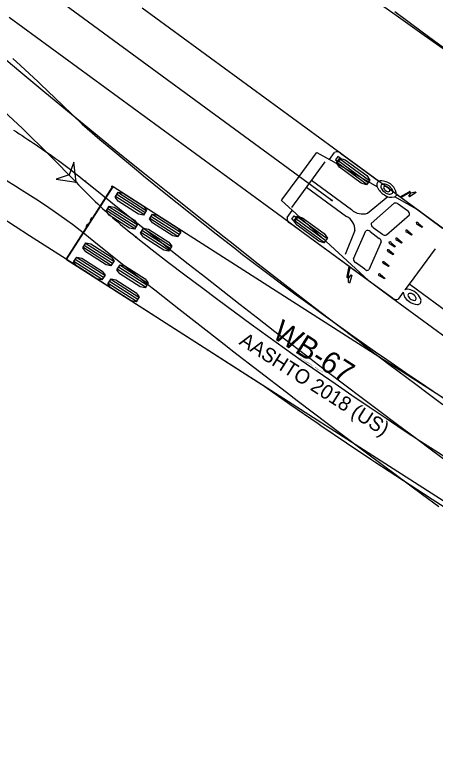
# Model space of a CAD drawing. Extents: x 973688 to 979179, y 703586 to 707602.
# Drawn here: x 978008.3 to 978049.6, y 704270.8 to 704344.1 of the extents above; entities that cross this region are included whole.
import ezdxf

# ---------------------------------------------------------------- set-up
doc = ezdxf.new("R2010")
doc.units = 0
for name, color, linetype in [('NB Left', 7, 'Continuous'), ('NB Right', 7, 'Continuous'), ('SB Left', 7, 'Continuous')]:
    doc.layers.add(name, color=color, linetype=linetype)

msp = doc.modelspace()

# ---------------------------------------------------------------- linework, layer by layer
at = {"layer": 'NB Left'}
for p, q in [((978039.485, 704325.851), (977941.886, 704397.375)), ((978036.259, 704328.216), (978037.951, 704330.525)), ((978037.951, 704330.525), (978037.989, 704330.576)), ((978037.989, 704330.576), (978039.234, 704329.865)), ((978039.241, 704329.872), (978039.747, 704330.563)), ((978040.066, 704330.187), (978039.823, 704329.854)), ((978040.354, 704329.976), (978040.066, 704330.187)), ((978040.341, 704330.493), (978044.087, 704327.748)), ((978038.786, 704329.632), (978035.498, 704325.145)), ((978039.234, 704329.865), (978039.241, 704329.872)), ((978043.95, 704327.175), (978039.236, 704329.865)), ((978039.823, 704329.854), (978040.11, 704329.644)), ((978039.964, 704329.607), (978042.922, 704327.439)), ((978040.1, 704329.792), (978043.057, 704327.624)), ((978040.11, 704329.644), (978040.354, 704329.976)), ((978040.235, 704329.976), (978043.193, 704327.809)), ((978034.566, 704325.906), (978036.259, 704328.216)), ((978037.474, 704327.842), (978041.42, 704324.951)), ((978036.981, 704327.169), (978040.926, 704324.278)), ((978046.209, 704326.204), (978047.079, 704326.689)), ((978047.137, 704326.623), (978046.281, 704326.14)), ((978047.048, 704326.272), (978047.241, 704326.562)), ((978047.763, 704326.64), (978047.131, 704326.211)), ((978047.138, 704326.623), (978047.137, 704326.623)), ((978047.174, 704326.611), (978047.138, 704326.623)), ((978047.175, 704326.611), (978047.174, 704326.611)), ((978047.176, 704326.61), (978047.175, 704326.611)), ((978047.241, 704326.564), (978047.176, 704326.61)), ((978047.213, 704326.646), (978047.283, 704326.595)), ((978047.241, 704326.563), (978047.257, 704326.587)), ((978047.241, 704326.562), (978047.241, 704326.564)), ((978047.257, 704326.587), (978047.283, 704326.595)), ((978047.283, 704326.595), (978047.286, 704326.595)), ((978047.286, 704326.595), (978047.665, 704326.711)), ((978047.665, 704326.711), (978047.668, 704326.711)), ((978047.668, 704326.711), (978047.764, 704326.641)), ((978047.764, 704326.641), (978047.763, 704326.64)), ((978034.529, 704325.855), (978034.566, 704325.906)), ((978035.582, 704324.881), (978034.529, 704325.855)), ((978042.999, 704324.602), (978044.978, 704326.227)), ((978048.096, 704324.81), (978045.658, 704326.201)), ((978045.851, 704326.455), (978046.194, 704326.204)), ((978046.194, 704326.204), (978046.209, 704326.204)), ((978046.281, 704326.14), (978046.2, 704326.199)), ((978046.281, 704326.14), (978050.456, 704323.08)), ((978047.131, 704326.211), (978047.048, 704326.272)), ((978045.612, 704325.568), (978043.356, 704323.581)), ((978046.92, 704324.814), (978046.008, 704325.483)), ((978035.071, 704324.182), (978035.578, 704324.873)), ((978035.526, 704323.991), (978035.77, 704324.324)), ((978035.578, 704324.873), (978035.582, 704324.881)), ((978043.072, 704317.954), (978035.583, 704324.88)), ((978035.77, 704324.324), (978036.057, 704324.113)), ((978044.846, 704322.449), (978047.102, 704324.436)), ((978041.17, 704319.348), (978035.316, 704323.637)), ((978035.813, 704323.78), (978035.526, 704323.991)), ((978035.777, 704323.893), (978038.735, 704321.726)), ((978036.057, 704324.113), (978035.813, 704323.78)), ((978035.913, 704324.078), (978038.87, 704321.911)), ((978036.048, 704324.263), (978039.006, 704322.096)), ((978047.987, 704323.619), (978048.407, 704323.263)), ((978041.734, 704322.877), (978040.786, 704320.513)), ((978041.6, 704320.094), (978042.816, 704322.844)), ((978043.538, 704323.202), (978044.45, 704322.534)), ((978046.956, 704322.865), (978047.377, 704322.509)), ((978048.354, 704323.19), (978047.888, 704323.484)), ((978048.407, 704323.263), (978048.354, 704323.19)), ((978043.231, 704322.785), (978044.143, 704322.116)), ((978047.323, 704322.436), (978046.857, 704322.73)), ((978047.377, 704322.509), (978047.323, 704322.436)), ((978044.344, 704321.764), (978043.129, 704319.015)), ((978045.668, 704321.265), (978045.201, 704321.558)), ((978045.301, 704321.693), (978045.721, 704321.337)), ((978046.334, 704321.652), (978045.868, 704321.945)), ((978045.967, 704322.081), (978046.387, 704321.724)), ((978046.387, 704321.724), (978046.334, 704321.652)), ((978045.499, 704320.512), (978045.033, 704320.806)), ((978045.132, 704320.941), (978045.552, 704320.585)), ((978045.721, 704321.337), (978045.668, 704321.265)), ((978049.637, 704321.096), (978047.078, 704317.603)), ((978045.552, 704320.585), (978045.499, 704320.512)), ((978040.973, 704318.358), (978041.174, 704319.333)), ((978041.257, 704319.284), (978041.054, 704318.322)), ((978041.174, 704319.333), (978041.17, 704319.348)), ((978041.257, 704319.284), (978041.176, 704319.343)), ((978045.432, 704316.224), (978041.257, 704319.284)), ((978042.713, 704319.074), (978041.801, 704319.742)), ((978045.049, 704319.333), (978044.562, 704319.64)), ((978044.661, 704319.776), (978045.102, 704319.405)), ((978045.102, 704319.405), (978045.049, 704319.333)), ((978041.143, 704318.241), (978041.362, 704318.513)), ((978041.445, 704318.452), (978041.227, 704317.72)), ((978041.362, 704318.513), (978041.445, 704318.452)), ((978044.273, 704318.552), (978044.694, 704318.195)), ((978041.054, 704318.322), (978041.054, 704318.321)), ((978041.054, 704318.321), (978041.076, 704318.29)), ((978041.124, 704318.192), (978041.055, 704318.243)), ((978041.076, 704318.29), (978041.077, 704318.289)), ((978041.077, 704318.289), (978041.078, 704318.289)), ((978041.078, 704318.289), (978041.142, 704318.241)), ((978041.125, 704318.189), (978041.124, 704318.192)), ((978041.142, 704318.241), (978041.125, 704318.219)), ((978041.125, 704318.219), (978041.125, 704318.191)), ((978041.129, 704317.792), (978041.125, 704318.189)), ((978041.13, 704317.789), (978041.129, 704317.792)), ((978041.225, 704317.719), (978041.13, 704317.789)), ((978041.142, 704318.241), (978041.143, 704318.241)), ((978041.227, 704317.72), (978041.225, 704317.719)), ((978044.641, 704318.123), (978044.174, 704318.416)), ((978044.694, 704318.195), (978044.641, 704318.123)), ((978047.077, 704317.602), (978046.672, 704317.049)), ((978047.27, 704317.462), (978047.077, 704317.602)), ((978055.628, 704311.337), (978047.27, 704317.462)), ((978046.505, 704316.822), (978046.006, 704316.14))]:
    msp.add_line(p, q, dxfattribs=at)
for points in [[(978020.806, 704344.809), (978023.495, 704342.838), (978026.183, 704340.868), (978028.872, 704338.898), (978031.561, 704336.927), (978034.249, 704334.957), (978036.938, 704332.987), (978039.626, 704331.017), (978042.315, 704329.047), (978045.003, 704327.077), (978047.691, 704325.106), (978050.38, 704323.136)], [(978050.732, 704312.34), (978048.044, 704314.31), (978045.355, 704316.28), (978042.667, 704318.25), (978039.979, 704320.22), (978037.29, 704322.191), (978034.602, 704324.161), (978031.913, 704326.131), (978029.225, 704328.101), (978026.536, 704330.071), (978023.848, 704332.042), (978021.159, 704334.012), (978018.47, 704335.982), (978015.782, 704337.953), (978013.093, 704339.923), (978010.404, 704341.893), (978007.716, 704343.864)]]:
    msp.add_lwpolyline(points, dxfattribs=at)
for points in [[(978039.931, 704329.561), (978040.269, 704330.022), (978040.785, 704329.858), (978042.914, 704328.297), (978043.226, 704327.855), (978042.888, 704327.394), (978042.372, 704327.558), (978040.243, 704329.118)], [(978035.744, 704323.847), (978036.082, 704324.309), (978036.598, 704324.144), (978038.727, 704322.584), (978039.039, 704322.141), (978038.701, 704321.68), (978038.185, 704321.845), (978036.056, 704323.405)]]:
    msp.add_lwpolyline(points, close=True, dxfattribs=at)
msp.add_circle((978039.485, 704325.851), 0.0417, dxfattribs=at)
for centre, radius, start, end in [((978040, 704330.147), 0.486, 45.35086, 121.30197), ((978044.324, 704327.377), 0.425, 121.82787, 208.36423), ((978044.334, 704326.238), 1.53, 8.25767, 99.26672), ((978044.65, 704327.203), 0.366, 151.81727, 224.29826), ((978044.648, 704326.828), 0.634, 44.3488, 120.35051), ((978044.74, 704327.01), 0.223, 60.99983, 130.60233), ((978044.51, 704326.428), 1.03, 26.58858, 54.97509), ((978045.51, 704327.86), 1.704, 203.68562, 239.59368), ((978045.363, 704327.628), 1.189, 214.89613, 250.78545), ((978044.73, 704327.098), 0.158, 148.73615, 210.24891), ((978045.107, 704327.278), 0.575, 206.84005, 243.41038), ((978044.642, 704326.653), 0.589, 26.52046, 69.50317), ((978045.009, 704326.972), 0.263, 232.69984, 306.60177), ((978045.154, 704326.905), 0.44, 245.55918, 309.37202), ((978045.016, 704326.843), 0.17, 331.434, 25.49833), ((978045.16, 704326.725), 0.317, 329.61513, 31.20753), ((978047.127, 704326.669), 0.0522, 52.64753, 157.50215), ((978047.109, 704326.615), 0.108, 16.74126, 62.92376), ((978045.34, 704327.291), 1.136, 232.46947, 286.27204), ((978045.506, 704326.512), 0.347, 296.09214, 350.90273), ((978045.74, 704325.204), 0.387, 46.20012, 109.43208), ((978042.486, 704326.029), 1.517, 225.34498, 289.77239), ((978046.779, 704324.514), 0.332, 346.42153, 64.84353), ((978035.543, 704324.066), 0.486, 166.2279, 242.179), ((978040.219, 704322.936), 1.517, 357.75747, 62.18489), ((978043.635, 704323.482), 0.296, 160.48369, 250.78137), ((978047.96, 704323.653), 0.184, 174.91974, 246.81175), ((978047.856, 704323.534), 0.157, 33.10929, 120.21895), ((978042.994, 704322.607), 0.296, 36.7485, 127.04617), ((978046.93, 704322.899), 0.184, 174.91974, 246.81175), ((978046.825, 704322.78), 0.157, 33.10929, 120.21895), ((978043.958, 704321.777), 0.387, 358.10023, 61.3273), ((978044.717, 704322.813), 0.387, 226.20257, 289.42963), ((978045.94, 704322.114), 0.184, 174.91974, 246.81175), ((978045.836, 704321.995), 0.157, 33.10929, 120.21895), ((978045.243, 704321.709), 0.157, 167.31091, 254.42058), ((978045.169, 704321.608), 0.157, 33.10929, 120.21895), ((978045.075, 704320.957), 0.157, 167.31091, 254.42058), ((978044.993, 704320.821), 0.184, 40.71811, 112.61013), ((978041.987, 704320.082), 0.387, 178.09778, 241.32975), ((978044.625, 704319.777), 0.157, 167.31091, 254.42058), ((978044.542, 704319.642), 0.184, 40.71811, 112.61013), ((978042.957, 704319.299), 0.332, 222.68634, 301.10834), ((978044.216, 704318.567), 0.157, 167.31091, 254.42058), ((978044.134, 704318.432), 0.184, 40.71811, 112.61013), ((978041.007, 704318.318), 0.0522, 130.02772, 234.88234), ((978041.053, 704318.351), 0.108, 224.60611, 270.7886), ((978046.946, 704316.374), 0.729, 69.57342, 112.08742), ((978046.677, 704315.407), 1.73, 47.59157, 72.39008), ((978047.639, 704316.889), 1.136, 183.39487, 238.18616), ((978047.136, 704316.538), 0.169, 82.19926, 182.31798), ((978047.484, 704316.611), 0.522, 188.7703, 235.93442), ((978047.097, 704315.976), 0.732, 38.93876, 85.17319), ((978047.42, 704316.171), 0.362, 358.06149, 47.10248), ((978047.13, 704315.802), 1.136, 9.5289, 51.04964), ((978045.798, 704316.723), 0.619, 233.76291, 289.60462), ((978047.918, 704317.035), 1.416, 231.69308, 268.76094), ((978047.63, 704316.677), 0.664, 228.66876, 266.89048), ((978047.612, 704316.185), 0.172, 264.06654, 351.21713), ((978047.905, 704315.964), 0.346, 267.15763, 4.17069)]:
    msp.add_arc(centre, radius, start, end, dxfattribs=at)
for centre, major_axis, start_param, end_param in [((978047.145, 704326.668), (-0.0631, 0.0462), 0.569648, 1.840391), ((978047.145, 704326.668), (-0.0631, 0.0462), 2.398717, 3.668019), ((978041.013, 704318.3), (0.0631, -0.0462), 1.301202, 2.571945), ((978041.013, 704318.3), (-0.0631, 0.0462), 2.615166, 3.884468)]:
    msp.add_ellipse(centre, major_axis=major_axis, ratio=0.544872, start_param=start_param, end_param=end_param, dxfattribs=at)
at = {"layer": 'NB Right'}
for points in [[(978051.333, 704340.134), (978048.57, 704342.09), (978045.808, 704344.046), (978043.043, 704346.004)], [(978051.075, 704340.396), (978048.364, 704342.406), (978045.658, 704344.42)]]:
    msp.add_lwpolyline(points, dxfattribs=at)
msp.add_arc((978976.317, 705591.808), 1552.257, 233.034975, 233.917416, dxfattribs=at)
at = {"layer": 'SB Left'}
for p, q in [((978017.887, 704327.233), (978017.876, 704327.215)), ((978017.947, 704327.195), (978017.887, 704327.233)), ((978013.366, 704320.036), (978017.947, 704327.196)), ((978017.862, 704327.194), (978015.903, 704324.132)), ((978017.862, 704327.195), (978017.862, 704327.194)), ((978022.721, 704324.142), (978017.947, 704327.195)), ((978021.201, 704324.842), (978018.421, 704326.621)), ((978020.954, 704324.456), (978018.174, 704326.235)), ((978021.077, 704324.649), (978018.297, 704326.428)), ((978020.188, 704323.259), (978017.408, 704325.038)), ((978020.311, 704323.453), (978017.532, 704325.231)), ((978020.064, 704323.066), (978017.285, 704324.845)), ((978024.57, 704322.687), (978021.79, 704324.465)), ((978015.737, 704323.872), (978015.456, 704323.433)), ((978015.597, 704323.654), (978015.657, 704323.616)), ((978015.823, 704324.138), (978015.68, 704323.913)), ((978015.74, 704323.878), (978015.884, 704324.101)), ((978015.825, 704324.139), (978015.823, 704324.138)), ((978015.883, 704324.102), (978015.825, 704324.139)), ((978015.903, 704324.132), (978015.883, 704324.102)), ((978024.323, 704322.301), (978021.543, 704324.079)), ((978024.446, 704322.494), (978021.667, 704324.272)), ((978062.473, 704298.709), (978022.721, 704324.142)), ((978015.292, 704323.176), (978013.332, 704320.114)), ((978015.396, 704323.47), (978015.252, 704323.246)), ((978015.252, 704323.246), (978015.252, 704323.244)), ((978015.252, 704323.244), (978015.311, 704323.207)), ((978015.311, 704323.207), (978015.292, 704323.176)), ((978015.311, 704323.206), (978015.454, 704323.43)), ((978023.557, 704321.104), (978020.777, 704322.882)), ((978023.681, 704321.297), (978020.901, 704323.075)), ((978023.434, 704320.911), (978020.654, 704322.689)), ((978017.879, 704319.651), (978015.1, 704321.43)), ((978018.003, 704319.844), (978015.223, 704321.623)), ((978017.756, 704319.458), (978014.976, 704321.237)), ((978013.319, 704320.093), (978013.307, 704320.075)), ((978013.307, 704320.075), (978013.367, 704320.037)), ((978013.332, 704320.114), (978013.332, 704320.113)), ((978013.367, 704320.037), (978018.14, 704316.982)), ((978016.99, 704318.262), (978014.21, 704320.04)), ((978017.114, 704318.455), (978014.334, 704320.233)), ((978016.867, 704318.068), (978014.087, 704319.847)), ((978021.249, 704317.496), (978018.469, 704319.274)), ((978021.372, 704317.689), (978018.593, 704319.467)), ((978021.125, 704317.303), (978018.346, 704319.081)), ((978020.36, 704316.106), (978017.58, 704317.884)), ((978020.483, 704316.299), (978017.703, 704318.077)), ((978020.236, 704315.913), (978017.456, 704317.691)), ((978018.14, 704316.982), (978057.892, 704291.549))]:
    msp.add_line(p, q, dxfattribs=at)
for points in [[(978006.117, 704340.76), (978008.675, 704338.622), (978011.235, 704336.497), (978013.798, 704334.384), (978016.367, 704332.282), (978017.139, 704331.653), (978018.943, 704330.188), (978021.526, 704328.104), (978023.339, 704326.65), (978024.117, 704326.029), (978026.714, 704323.962), (978029.319, 704321.905), (978029.58, 704321.7), (978031.931, 704319.856), (978034.55, 704317.817), (978035.862, 704316.801), (978037.176, 704315.787), (978039.809, 704313.766), (978042.185, 704311.955), (978042.45, 704311.754), (978045.097, 704309.751), (978047.751, 704307.758), (978048.814, 704306.963), (978050.412, 704305.773)], [(978008.078, 704339.817), (978008.826, 704339.134), (978010.552, 704337.53), (978010.796, 704337.3), (978012.975, 704335.214), (978014.883, 704333.346), (978015.388, 704332.915), (978016.649, 704331.845), (978017.911, 704330.784), (978020.436, 704328.688), (978020.941, 704328.273), (978022.968, 704326.623), (978025.516, 704324.581), (978028.09, 704322.555), (978029.909, 704321.145), (978030.692, 704320.543), (978033.319, 704318.549), (978034.376, 704317.757), (978035.967, 704316.576), (978037.564, 704315.403), (978038.632, 704314.627), (978041.044, 704312.893), (978041.312, 704312.702), (978044.01, 704310.801), (978044.551, 704310.424), (978046.723, 704308.925), (978048.086, 704307.997), (978049.453, 704307.074), (978050.826, 704306.161)], [(978008.136, 704332.766), (978008.417, 704332.587), (978008.698, 704332.408), (978008.978, 704332.227), (978009.257, 704332.045), (978009.536, 704331.862), (978009.814, 704331.678), (978010.091, 704331.494), (978010.368, 704331.308), (978010.644, 704331.12), (978010.919, 704330.932), (978011.193, 704330.743), (978011.466, 704330.552), (978011.739, 704330.36), (978012.011, 704330.167), (978012.282, 704329.973), (978012.552, 704329.777), (978012.821, 704329.581), (978013.089, 704329.382), (978013.356, 704329.183), (978013.622, 704328.982), (978013.887, 704328.78), (978014.151, 704328.576), (978014.414, 704328.371), (978014.675, 704328.165), (978014.936, 704327.957), (978015.195, 704327.748)], [(978014.298, 704327.638), (978014.07, 704329.625), (978013.603, 704328.357), (978012.32, 704327.932), (978014.298, 704327.638)], [(978050.014, 704295.695), (978048.396, 704296.885), (978045.704, 704298.877), (978043.02, 704300.877), (978042.751, 704301.078), (978040.342, 704302.887), (978037.671, 704304.907), (978036.072, 704306.123), (978035.007, 704306.935), (978032.35, 704308.973), (978029.7, 704311.02), (978029.171, 704311.43), (978027.058, 704313.076), (978024.422, 704315.141), (978022.056, 704317.008), (978021.794, 704317.216), (978019.173, 704319.299), (978016.559, 704321.392), (978014.992, 704322.65), (978013.932, 704323.468), (978013.393, 704323.867), (978012.027, 704324.841), (978011.193, 704325.408), (978010.35, 704325.964), (978008.925, 704326.867), (978008.349, 704327.221), (978005.465, 704328.988)], [(978014.298, 704327.638), (978014.53, 704327.398), (978014.762, 704327.16), (978014.996, 704326.922), (978015.231, 704326.686), (978015.467, 704326.45), (978015.704, 704326.216), (978015.943, 704325.983), (978016.183, 704325.752), (978016.424, 704325.521), (978016.666, 704325.292), (978016.909, 704325.064), (978017.154, 704324.838), (978017.4, 704324.613), (978017.647, 704324.39), (978017.896, 704324.168), (978018.146, 704323.948), (978018.398, 704323.729), (978018.65, 704323.512), (978018.905, 704323.296), (978019.16, 704323.082), (978019.417, 704322.87), (978019.676, 704322.659), (978019.936, 704322.451), (978020.197, 704322.244)], [(978052.185, 704294.62), (978049.345, 704296.419), (978048.495, 704296.964), (978046.516, 704298.244), (978043.7, 704300.093), (978043.419, 704300.279), (978040.9, 704301.966), (978038.394, 704303.671), (978038.117, 704303.861), (978035.35, 704305.78), (978032.871, 704307.519), (978032.588, 704307.701), (978029.754, 704309.52), (978026.918, 704311.34), (978024.077, 704313.164), (978021.224, 704314.995), (978018.356, 704316.836), (978015.477, 704318.684), (978012.596, 704320.531), (978009.727, 704322.374), (978006.876, 704324.204)]]:
    msp.add_lwpolyline(points, dxfattribs=at)
for points in [[(978014.298, 704327.638), (978014.07, 704329.625), (978013.603, 704328.357), (978012.32, 704327.932)], [(978021.231, 704324.89), (978020.923, 704324.408), (978020.441, 704324.512), (978018.439, 704325.793), (978018.143, 704326.187), (978018.451, 704326.669), (978018.933, 704326.565), (978020.935, 704325.284)], [(978020.342, 704323.5), (978020.034, 704323.019), (978019.552, 704323.122), (978017.55, 704324.403), (978017.254, 704324.797), (978017.562, 704325.279), (978018.044, 704325.175), (978020.046, 704323.895)], [(978024.601, 704322.735), (978024.292, 704322.253), (978023.81, 704322.357), (978021.809, 704323.637), (978021.513, 704324.031), (978021.821, 704324.513), (978022.303, 704324.409), (978024.304, 704323.129)], [(978023.711, 704321.345), (978023.403, 704320.863), (978022.921, 704320.967), (978020.92, 704322.247), (978020.623, 704322.641), (978020.932, 704323.123), (978021.414, 704323.019), (978023.415, 704321.739)], [(978018.034, 704319.892), (978017.725, 704319.41), (978017.243, 704319.514), (978015.242, 704320.795), (978014.946, 704321.189), (978015.254, 704321.671), (978015.736, 704321.567), (978017.737, 704320.286)], [(978017.144, 704318.502), (978016.836, 704318.021), (978016.354, 704318.124), (978014.353, 704319.405), (978014.056, 704319.799), (978014.365, 704320.281), (978014.847, 704320.177), (978016.848, 704318.897)], [(978021.403, 704317.737), (978021.095, 704317.255), (978020.613, 704317.359), (978018.611, 704318.639), (978018.315, 704319.033), (978018.623, 704319.515), (978019.105, 704319.411), (978021.107, 704318.131)], [(978020.514, 704316.347), (978020.206, 704315.865), (978019.723, 704315.969), (978017.722, 704317.249), (978017.426, 704317.643), (978017.734, 704318.125), (978018.216, 704318.021), (978020.217, 704316.741)]]:
    msp.add_lwpolyline(points, close=True, dxfattribs=at)
for centre, radius in [((978014.298, 704327.638), 0.0417), ((978014.298, 704327.638), 0.0417), ((978015.195, 704327.748), 0.0417), ((978015.195, 704327.748), 0.0417), ((978017.84, 704327.223), 0.0266), ((978020.197, 704322.244), 0.0417), ((978020.197, 704322.244), 0.0417), ((978013.297, 704320.121), 0.0266)]:
    msp.add_circle(centre, radius, dxfattribs=at)
for centre, radius, start, end in [((977872.77, 704190.972), 196.743, 43.9988, 55.60052), ((978621.574, 705074.454), 961.907, 230.920921, 239.173561), ((978017.84, 704327.224), 0.0363, 346.46748, 307.62883), ((978015.709, 704323.894), 0.0352, 147.4153, 326.41571), ((978015.71, 704323.895), 0.0353, 330.72621, 149.07586), ((978015.426, 704323.451), 0.0354, 151.68157, 323.86703), ((978015.426, 704323.451), 0.0352, 328.36436, 147.36476), ((978266.959, 704636.917), 399.889, 231.89697, 241.1915), ((978011.616, 704321.182), 2.022, 327.39003, 328.07379)]:
    msp.add_arc(centre, radius, start, end, dxfattribs=at)

# ---------------------------------------------------------------- texts
for s, height, p in [('WB-67', 2.125, (978033.477, 704312.417)), ('AASHTO 2018 (US)', 1.41667, (978030.254, 704311.746)), ('(c) 2022 Transoft Solutions, Inc. All rights reserved.', 0.085, (978036.371, 704310.313))]:
    msp.add_text(s, height=height, rotation=327.39003, dxfattribs=at).set_placement(p)

doc.saveas('drawing.dxf')
